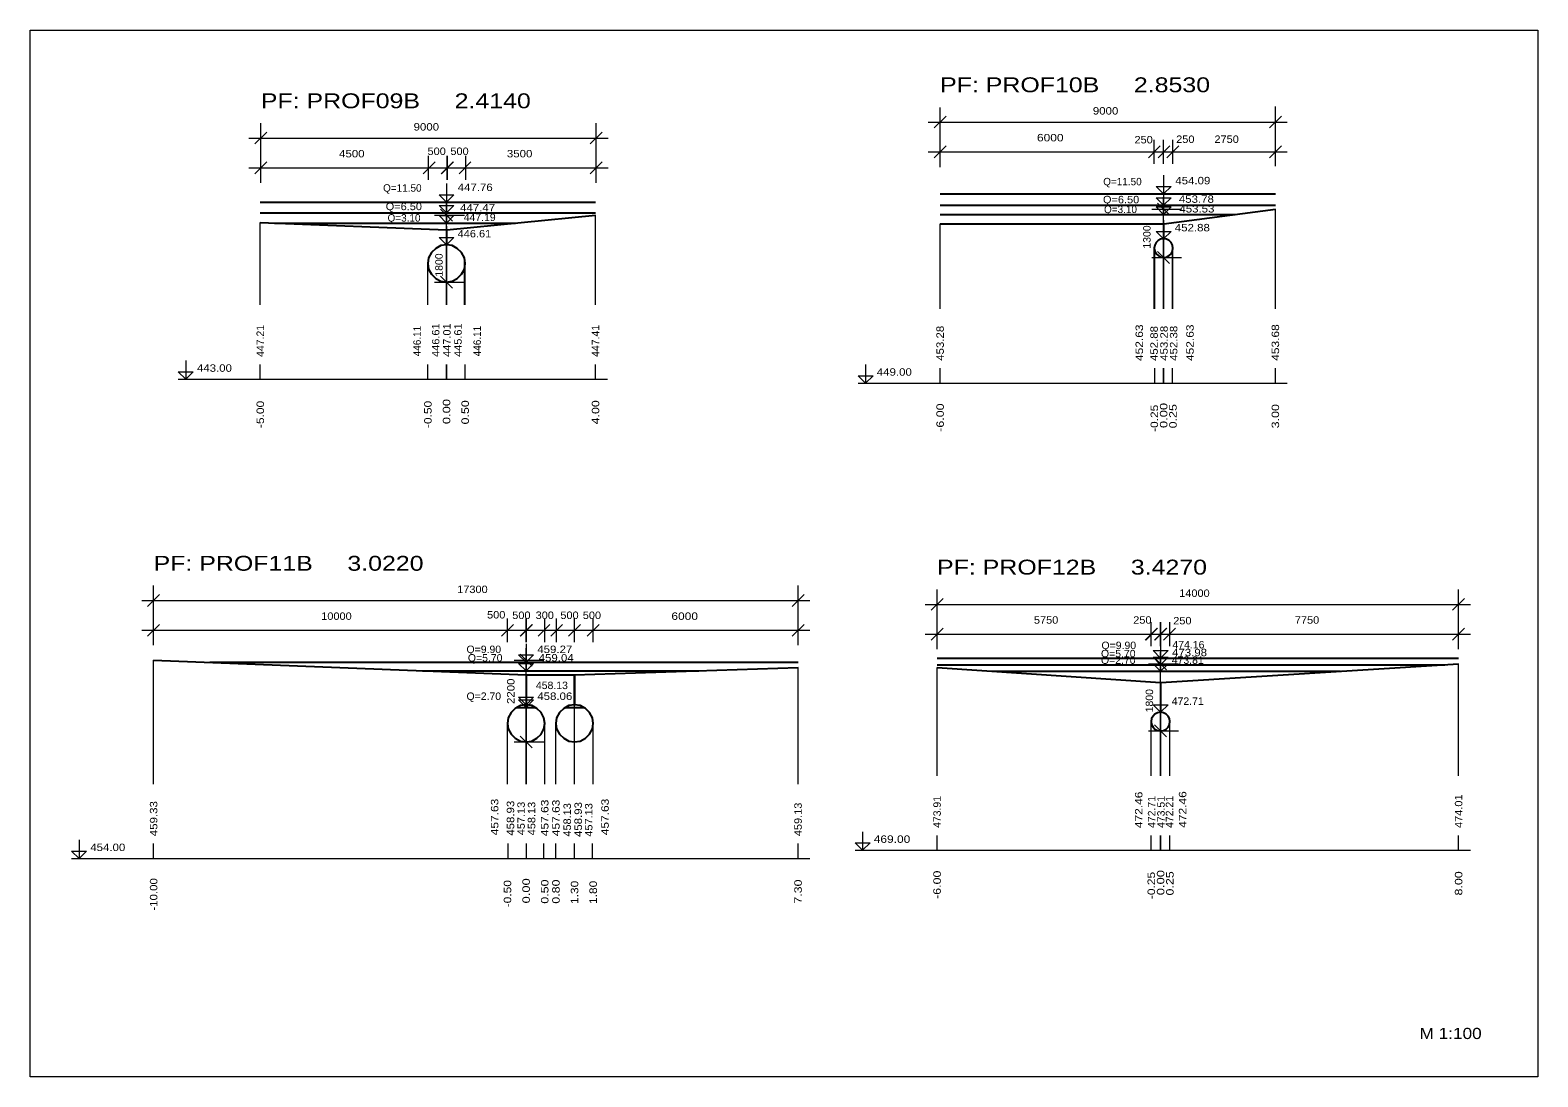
# Model space of a CAD drawing. Extents: x 7 to 442, y -393 to 441.
# Drawn here: x 17.93 to 58.4, y 45.74 to 73.86 of the extents above; entities that cross this region are included whole.
import ezdxf
from ezdxf.enums import TextEntityAlignment as Align

# ---------------------------------------------------------------- set-up
doc = ezdxf.new("R2010")
doc.units = 0
doc.header["$LTSCALE"] = 0.08
doc.header["$PDMODE"] = 32
doc.header["$PDSIZE"] = 0.04
doc.layers.add('63', color=7, linetype='Continuous', lineweight=13)
doc.layers.add('7', color=7, linetype='Continuous', lineweight=13)

msp = doc.modelspace()

# ---------------------------------------------------------------- linework, layer by layer
at = {"layer": '63'}
msp.add_lwpolyline([(17.927, 45.74), (17.927, 73.856), (38.164, 73.856), (58.401, 73.856), (58.401, 45.74), (38.164, 45.74)], close=True, dxfattribs=at)
at = {"layer": '7'}
for p, q in [((42.355, 70.174), (42.355, 71.774)), ((51.355, 70.201), (51.355, 71.801)), ((24.12, 69.758), (24.12, 71.358)), ((33.12, 69.758), (33.12, 71.358)), ((42.035, 71.388), (51.675, 71.388)), ((42.195, 71.228), (42.515, 71.548)), ((51.195, 71.228), (51.515, 71.548)), ((23.8, 70.958), (33.44, 70.958)), ((23.96, 70.798), (24.28, 71.118)), ((32.96, 70.798), (33.28, 71.118)), ((42.355, 70.268), (42.355, 70.908)), ((48.105, 70.268), (48.105, 70.908)), ((48.355, 70.268), (48.355, 70.908)), ((48.355, 70.268), (48.355, 70.908)), ((48.355, 70.268), (48.355, 70.908)), ((48.605, 70.268), (48.605, 70.908)), ((51.355, 70.268), (51.355, 70.908)), ((24.12, 69.838), (24.12, 70.478)), ((28.62, 69.838), (28.62, 70.478)), ((29.12, 69.838), (29.12, 70.478)), ((29.12, 69.838), (29.12, 70.478)), ((29.12, 69.838), (29.12, 70.478)), ((29.13, 69.838), (29.13, 70.478)), ((29.13, 69.838), (29.13, 70.478)), ((29.62, 69.838), (29.62, 70.478)), ((33.12, 69.838), (33.12, 70.478)), ((42.035, 70.588), (51.675, 70.588)), ((42.195, 70.428), (42.515, 70.748)), ((47.945, 70.428), (48.265, 70.748)), ((48.205, 70.428), (48.525, 70.748)), ((48.205, 70.428), (48.525, 70.748)), ((48.445, 70.428), (48.765, 70.748)), ((51.195, 70.428), (51.515, 70.748)), ((23.8, 70.158), (33.44, 70.158)), ((23.96, 69.998), (24.28, 70.318)), ((28.48, 69.998), (28.8, 70.318)), ((28.96, 69.998), (29.28, 70.318)), ((28.96, 69.998), (29.28, 70.318)), ((28.96, 69.998), (29.28, 70.318)), ((28.97, 69.998), (29.29, 70.318)), ((28.97, 69.998), (29.29, 70.318)), ((29.44, 69.998), (29.76, 70.318)), ((29.44, 69.998), (29.76, 70.318)), ((32.96, 69.998), (33.28, 70.318)), ((48.515, 68.891), (48.195, 69.211)), ((48.355, 67.591), (48.355, 69.371)), ((28.784, 68.889), (29.584, 68.889)), ((29.264, 68.729), (28.944, 69.049)), ((29.104, 66.929), (29.104, 69.209)), ((33.104, 66.479), (33.104, 68.889)), ((48.035, 69.051), (48.835, 69.051)), ((51.355, 66.374), (51.355, 69.051)), ((24.104, 66.479), (24.104, 68.689)), ((29.104, 66.479), (29.104, 68.489)), ((29.114, 66.479), (29.114, 68.489)), ((42.355, 66.374), (42.355, 68.651)), ((48.355, 66.374), (48.355, 68.651)), ((48.365, 66.374), (48.365, 68.651)), ((29.104, 66.479), (29.104, 68.089)), ((29.104, 68.089), (29.114, 68.089)), ((29.114, 66.479), (29.114, 68.089)), ((48.105, 66.374), (48.105, 68.001)), ((48.115, 66.374), (48.115, 68.081)), ((48.355, 66.374), (48.355, 68.251)), ((48.355, 68.251), (48.365, 68.251)), ((48.365, 66.374), (48.365, 68.251)), ((48.595, 66.374), (48.595, 68.081)), ((48.605, 66.374), (48.605, 68.001)), ((29.584, 66.479), (29.584, 67.739)), ((48.035, 67.751), (48.835, 67.751)), ((48.115, 66.374), (48.115, 67.921)), ((48.515, 67.591), (48.195, 67.911)), ((48.355, 66.374), (48.355, 67.751)), ((48.595, 66.374), (48.595, 67.921)), ((28.604, 66.479), (28.604, 67.589)), ((29.264, 66.929), (28.944, 67.249)), ((29.604, 66.479), (29.604, 67.589)), ((28.784, 67.089), (29.584, 67.089)), ((29.104, 66.479), (29.104, 67.089)), ((24.104, 64.479), (24.104, 64.879)), ((28.604, 64.479), (28.604, 64.879)), ((29.104, 64.479), (29.104, 64.879)), ((29.104, 64.479), (29.104, 64.879)), ((29.104, 64.479), (29.104, 64.879)), ((29.114, 64.479), (29.114, 64.879)), ((29.114, 64.479), (29.114, 64.879)), ((29.604, 64.479), (29.604, 64.879)), ((33.104, 64.479), (33.104, 64.879)), ((42.355, 64.374), (42.355, 64.774)), ((48.115, 64.374), (48.115, 64.774)), ((48.355, 64.374), (48.355, 64.774)), ((48.365, 64.374), (48.365, 64.774)), ((48.365, 64.374), (48.365, 64.774)), ((48.595, 64.374), (48.595, 64.774)), ((51.355, 64.374), (51.355, 64.774)), ((21.904, 64.479), (33.424, 64.479)), ((40.155, 64.374), (51.675, 64.374)), ((21.081, 58.375), (21.401, 58.695)), ((21.241, 57.335), (21.241, 58.935)), ((38.381, 58.375), (38.701, 58.695)), ((38.541, 57.335), (38.541, 58.935)), ((42.273, 57.232), (42.273, 58.832)), ((56.273, 57.232), (56.273, 58.832)), ((20.921, 58.535), (38.861, 58.535)), ((41.953, 58.432), (56.593, 58.432)), ((42.113, 58.272), (42.433, 58.592)), ((56.113, 58.272), (56.433, 58.592)), ((21.081, 57.575), (21.401, 57.895)), ((21.241, 57.415), (21.241, 58.055)), ((30.581, 57.575), (30.901, 57.895)), ((30.741, 57.415), (30.741, 58.055)), ((31.081, 57.575), (31.401, 57.895)), ((31.081, 57.575), (31.401, 57.895)), ((31.091, 57.575), (31.411, 57.895)), ((31.091, 57.575), (31.411, 57.895)), ((31.241, 57.415), (31.241, 58.055)), ((31.241, 57.415), (31.241, 58.055)), ((31.241, 57.415), (31.241, 58.055)), ((31.251, 57.415), (31.251, 58.055)), ((31.561, 57.575), (31.881, 57.895)), ((31.741, 57.415), (31.741, 58.055)), ((31.901, 57.575), (32.221, 57.895)), ((31.901, 57.575), (32.221, 57.895)), ((32.061, 57.415), (32.061, 58.055)), ((32.061, 57.415), (32.061, 58.055)), ((32.381, 57.575), (32.701, 57.895)), ((32.381, 57.575), (32.701, 57.895)), ((32.381, 57.575), (32.701, 57.895)), ((32.381, 57.575), (32.701, 57.895)), ((32.381, 57.575), (32.701, 57.895)), ((32.541, 57.415), (32.541, 58.055)), ((32.541, 57.415), (32.541, 58.055)), ((32.541, 57.415), (32.541, 58.055)), ((32.541, 57.415), (32.541, 58.055)), ((32.541, 57.415), (32.541, 58.055)), ((32.881, 57.575), (33.201, 57.895)), ((33.041, 57.415), (33.041, 58.055)), ((38.381, 57.575), (38.701, 57.895)), ((38.541, 57.415), (38.541, 58.055)), ((42.273, 57.312), (42.273, 57.952)), ((48.023, 57.312), (48.023, 57.952)), ((48.273, 57.312), (48.273, 57.952)), ((48.273, 57.312), (48.273, 57.952)), ((48.273, 57.312), (48.273, 57.952)), ((48.283, 57.312), (48.283, 57.952)), ((48.283, 57.312), (48.283, 57.952)), ((48.523, 57.312), (48.523, 57.952)), ((56.273, 57.312), (56.273, 57.952)), ((20.921, 57.735), (38.861, 57.735)), ((41.953, 57.632), (56.593, 57.632)), ((42.113, 57.472), (42.433, 57.792)), ((47.863, 57.472), (48.183, 57.792)), ((47.873, 57.472), (48.193, 57.792)), ((48.113, 57.472), (48.433, 57.792)), ((48.113, 57.472), (48.433, 57.792)), ((48.123, 57.472), (48.443, 57.792)), ((48.123, 57.472), (48.443, 57.792)), ((48.353, 57.472), (48.673, 57.792)), ((48.353, 57.472), (48.673, 57.792)), ((56.113, 57.472), (56.433, 57.792)), ((31.401, 56.775), (31.081, 57.095)), ((31.241, 54.575), (31.241, 57.255)), ((48.273, 54.872), (48.273, 57.152)), ((21.241, 53.605), (21.241, 56.935)), ((30.921, 56.935), (31.721, 56.935)), ((38.541, 53.605), (38.541, 56.735)), ((42.273, 53.826), (42.273, 56.732)), ((47.953, 56.832), (48.753, 56.832)), ((48.433, 56.672), (48.113, 56.992)), ((56.273, 53.826), (56.273, 56.832)), ((31.241, 53.605), (31.241, 56.535)), ((31.251, 53.605), (31.251, 56.535)), ((32.541, 53.605), (32.541, 56.535)), ((32.541, 53.605), (32.541, 56.535)), ((48.273, 53.826), (48.273, 56.332)), ((48.283, 53.826), (48.283, 56.332)), ((31.241, 53.605), (31.241, 55.735)), ((31.241, 55.735), (31.251, 55.735)), ((31.251, 53.605), (31.251, 55.735)), ((32.541, 53.605), (32.541, 55.735)), ((32.541, 53.605), (32.541, 55.735)), ((48.273, 53.826), (48.273, 55.532)), ((48.273, 55.532), (48.283, 55.532)), ((48.283, 53.826), (48.283, 55.532)), ((30.741, 53.605), (30.741, 55.235)), ((31.741, 53.605), (31.741, 55.235)), ((32.041, 53.605), (32.041, 55.235)), ((33.041, 53.605), (33.041, 55.235)), ((48.023, 53.826), (48.023, 55.282)), ((48.433, 54.872), (48.113, 55.192)), ((48.523, 53.826), (48.523, 55.282)), ((30.921, 54.735), (31.721, 54.735)), ((31.401, 54.575), (31.081, 54.895)), ((31.241, 53.605), (31.241, 54.735)), ((32.541, 53.605), (32.541, 54.735)), ((47.953, 55.032), (48.753, 55.032)), ((48.273, 53.826), (48.273, 55.032)), ((42.273, 51.826), (42.273, 52.226)), ((48.023, 51.826), (48.023, 52.226)), ((48.273, 51.826), (48.273, 52.226)), ((48.283, 51.826), (48.283, 52.226)), ((48.283, 51.826), (48.283, 52.226)), ((48.523, 51.826), (48.523, 52.226)), ((56.273, 51.826), (56.273, 52.226)), ((21.241, 51.605), (21.241, 52.005)), ((30.761, 51.605), (30.761, 52.005)), ((31.251, 51.605), (31.251, 52.005)), ((31.251, 51.605), (31.251, 52.005)), ((31.721, 51.605), (31.721, 52.005)), ((32.041, 51.605), (32.041, 52.005)), ((32.541, 51.605), (32.541, 52.005)), ((32.541, 51.605), (32.541, 52.005)), ((32.541, 51.605), (32.541, 52.005)), ((32.541, 51.605), (32.541, 52.005)), ((32.541, 51.605), (32.541, 52.005)), ((33.021, 51.605), (33.021, 52.005)), ((38.541, 51.605), (38.541, 52.005)), ((40.073, 51.826), (56.593, 51.826)), ((19.041, 51.605), (38.861, 51.605))]:
    msp.add_line(p, q, dxfattribs=at)
at = {"layer": '7', "lineweight": 25}
for p, q in [((24.104, 69.236), (33.104, 69.236)), ((42.355, 69.46), (51.355, 69.46)), ((24.104, 68.949), (33.104, 68.949)), ((42.355, 69.155), (51.355, 69.155)), ((42.355, 68.907), (50.277, 68.907)), ((24.49, 68.674), (30.955, 68.674)), ((22.749, 56.875), (38.541, 56.875)), ((42.273, 56.99), (56.273, 56.99)), ((42.273, 56.809), (55.901, 56.809)), ((28.459, 56.646), (35.88, 56.646)), ((43.749, 56.634), (53.102, 56.634)), ((31.004, 55.665), (31.478, 55.665)), ((32.304, 55.665), (32.778, 55.665))]:
    msp.add_line(p, q, dxfattribs=at)
at = {"layer": '7'}
for points in [[(29.104, 69.736), (29.104, 69.236), (28.904, 69.436), (29.304, 69.436), (29.104, 69.236)], [(48.355, 69.96), (48.355, 69.46), (48.155, 69.66), (48.555, 69.66), (48.355, 69.46)], [(48.355, 69.655), (48.355, 69.155), (48.155, 69.355), (48.555, 69.355), (48.355, 69.155)], [(29.104, 69.449), (29.104, 68.949), (28.904, 69.149), (29.304, 69.149), (29.104, 68.949)], [(48.355, 69.407), (48.355, 68.907), (48.155, 69.107), (48.555, 69.107), (48.355, 68.907)], [(29.104, 69.174), (29.104, 68.674), (28.904, 68.874), (29.304, 68.874), (29.104, 68.674)], [(29.104, 68.589), (29.104, 68.089), (28.904, 68.289), (29.304, 68.289), (29.104, 68.089)], [(48.355, 68.751), (48.355, 68.251), (48.155, 68.451), (48.555, 68.451), (48.355, 68.251)], [(22.104, 64.979), (22.104, 64.479), (21.904, 64.679), (22.304, 64.679), (22.104, 64.479)], [(40.355, 64.874), (40.355, 64.374), (40.155, 64.574), (40.555, 64.574), (40.355, 64.374)], [(48.273, 57.49), (48.273, 56.99), (48.073, 57.19), (48.473, 57.19), (48.273, 56.99)], [(31.241, 57.375), (31.241, 56.875), (31.041, 57.075), (31.441, 57.075), (31.241, 56.875)], [(31.241, 57.146), (31.241, 56.646), (31.041, 56.846), (31.441, 56.846), (31.241, 56.646)], [(48.273, 57.309), (48.273, 56.809), (48.073, 57.009), (48.473, 57.009), (48.273, 56.809)], [(48.273, 57.134), (48.273, 56.634), (48.073, 56.834), (48.473, 56.834), (48.273, 56.634)], [(31.241, 56.235), (31.241, 55.735), (31.041, 55.935), (31.441, 55.935), (31.241, 55.735)], [(31.241, 56.165), (31.241, 55.665), (31.041, 55.865), (31.441, 55.865), (31.241, 55.665)], [(48.273, 56.032), (48.273, 55.532), (48.073, 55.732), (48.473, 55.732), (48.273, 55.532)], [(40.273, 52.326), (40.273, 51.826), (40.073, 52.026), (40.473, 52.026), (40.273, 51.826)], [(19.241, 52.105), (19.241, 51.605), (19.041, 51.805), (19.441, 51.805), (19.241, 51.605)]]:
    msp.add_lwpolyline(points, dxfattribs=at)
at = {"layer": '7', "lineweight": 25}
for points in [[(24.104, 68.689), (29.104, 68.489), (29.104, 68.089), (28.954, 68.069), (28.814, 67.989), (28.704, 67.879), (28.624, 67.739), (28.604, 67.589), (28.624, 67.439), (28.704, 67.299), (28.814, 67.189), (28.954, 67.109), (29.104, 67.089), (29.254, 67.109), (29.394, 67.189), (29.504, 67.299), (29.584, 67.439), (29.604, 67.589), (29.584, 67.739), (29.504, 67.879), (29.394, 67.989), (29.254, 68.069), (29.114, 68.089), (29.114, 68.489), (33.104, 68.889)], [(42.355, 68.651), (48.355, 68.651), (48.355, 68.251), (48.275, 68.241), (48.205, 68.201), (48.155, 68.151), (48.115, 68.081), (48.105, 68.001), (48.115, 67.921), (48.155, 67.851), (48.205, 67.801), (48.275, 67.761), (48.355, 67.751), (48.435, 67.761), (48.505, 67.801), (48.555, 67.851), (48.595, 67.921), (48.605, 68.001), (48.595, 68.081), (48.555, 68.151), (48.505, 68.201), (48.435, 68.241), (48.365, 68.251), (48.365, 68.651), (51.355, 69.051)], [(21.241, 56.935), (31.241, 56.535), (31.241, 55.735), (31.091, 55.715), (30.951, 55.635), (30.841, 55.525), (30.761, 55.385), (30.741, 55.235), (30.761, 55.085), (30.841, 54.945), (30.951, 54.835), (31.091, 54.755), (31.241, 54.735), (31.391, 54.755), (31.531, 54.835), (31.641, 54.945), (31.721, 55.085), (31.741, 55.235), (31.721, 55.385), (31.641, 55.525), (31.531, 55.635), (31.391, 55.715), (31.251, 55.735), (31.251, 56.535), (32.541, 56.535), (32.541, 55.735), (32.391, 55.715), (32.251, 55.635), (32.141, 55.525), (32.061, 55.385), (32.041, 55.235), (32.061, 55.085), (32.141, 54.945), (32.251, 54.835), (32.391, 54.755), (32.541, 54.735), (32.691, 54.755), (32.831, 54.835), (32.941, 54.945), (33.021, 55.085), (33.041, 55.235), (33.021, 55.385), (32.941, 55.525), (32.831, 55.635), (32.691, 55.715), (32.541, 55.735), (32.541, 56.535), (38.541, 56.735)], [(42.273, 56.732), (48.273, 56.332), (48.273, 55.532), (48.193, 55.522), (48.123, 55.482), (48.073, 55.432), (48.033, 55.362), (48.023, 55.282), (48.033, 55.202), (48.073, 55.132), (48.123, 55.082), (48.193, 55.042), (48.273, 55.032), (48.353, 55.042), (48.423, 55.082), (48.473, 55.132), (48.513, 55.202), (48.523, 55.282), (48.513, 55.362), (48.473, 55.432), (48.423, 55.482), (48.353, 55.522), (48.283, 55.532), (48.283, 56.332), (56.273, 56.832)]]:
    msp.add_lwpolyline(points, dxfattribs=at)
at = {"layer": '7'}
msp.add_point((32.541, 55.735), dxfattribs=at)

# ---------------------------------------------------------------- texts
at = {"layer": '63', "width": 1.15}
msp.add_text('M 1:100', height=0.3, dxfattribs=at).set_placement((56.06, 46.756), align=Align.CENTER)
at = {"layer": '7'}
for s, height, width, p in [('PF: PROF10B     2.8530', 0.4, 1.25, (42.355, 72.188)), ('PF: PROF09B     2.4140', 0.4, 1.25, (24.12, 71.758)), ('9000', 0.2, 1.15, (46.455, 71.588)), ('9000', 0.2, 1.15, (28.22, 71.158)), ('6000', 0.2, 1.2, (44.955, 70.868)), ('250', 0.2, 1.1, (47.573, 70.813)), ('250', 0.2, 1.1, (48.692, 70.826)), ('2750', 0.2, 1.1, (49.719, 70.827)), ('4500', 0.2, 1.15, (26.22, 70.438)), ('500', 0.2, 1.1, (28.594, 70.503)), ('500', 0.2, 1.1, (29.208, 70.503)), ('3500', 0.2, 1.15, (30.725, 70.438)), ('447.76', 0.2, 1.15, (29.404, 69.533)), ('454.09', 0.2, 1.15, (48.669, 69.715)), ('Q=6.50', 0.2, 1.1, (27.472, 69.02)), ('Q=6.50', 0.2, 1.1, (46.727, 69.205)), ('453.78', 0.2, 1.15, (48.764, 69.218)), ('447.47', 0.2, 1.15, (29.469, 68.987)), ('447.19', 0.2, 1.05, (29.565, 68.729)), ('453.53', 0.2, 1.15, (48.778, 68.957)), ('446.61', 0.2, 1.1, (29.404, 68.289)), ('452.88', 0.2, 1.15, (48.655, 68.451)), ('443.00', 0.2, 1.15, (22.404, 64.679)), ('449.00', 0.2, 1.15, (40.655, 64.574)), ('PF: PROF11B     3.0220', 0.4, 1.25, (21.241, 59.335)), ('PF: PROF12B     3.4270', 0.4, 1.25, (42.273, 59.232)), ('17300', 0.2, 1.1, (29.391, 58.735)), ('14000', 0.2, 1.1, (48.773, 58.632)), ('10000', 0.2, 1.1, (25.741, 58.015)), ('500', 0.2, 1.1, (30.193, 58.052)), ('500', 0.2, 1.1, (30.869, 58.039)), ('300', 0.2, 1.1, (31.496, 58.04)), ('500', 0.2, 1.1, (32.16, 58.04)), ('500', 0.2, 1.1, (32.762, 58.039)), ('6000', 0.2, 1.2, (35.141, 58.015)), ('5750', 0.2, 1.1, (44.873, 57.912)), ('250', 0.2, 1.1, (47.539, 57.912)), ('250', 0.2, 1.1, (48.613, 57.894)), ('7750', 0.2, 1.1, (51.878, 57.912)), ('Q=9.90', 0.2, 1.05, (29.641, 57.124)), ('Q=5.70', 0.2, 1.05, (29.678, 56.895)), ('459.27', 0.2, 1.15, (31.541, 57.124)), ('459.04', 0.2, 1.15, (31.578, 56.896)), ('Q=5.70', 0.2, 1.05, (46.673, 57.009)), ('Q=9.90', 0.2, 1.05, (46.687, 57.23)), ('473.98', 0.2, 1.15, (48.58, 57.038)), ('474.16', 0.2, 1.05, (48.591, 57.248)), ('Q=2.70', 0.2, 1.05, (46.673, 56.834)), ('473.81', 0.2, 1.05, (48.573, 56.834)), ('458.13', 0.2, 1.05, (31.504, 56.156)), ('Q=2.70', 0.2, 1.05, (29.641, 55.865)), ('458.06', 0.2, 1.15, (31.541, 55.865)), ('472.71', 0.2, 1.05, (48.573, 55.732)), ('469.00', 0.2, 1.2, (40.573, 52.026)), ('454.00', 0.2, 1.15, (19.541, 51.805))]:
    msp.add_text(s, height=height, dxfattribs=dict(at, width=width)).set_placement(p)
for s, p in [('Q=11.50', (27.401, 69.517)), ('Q=11.50', (46.733, 69.688)), ('Q=3.10', (27.521, 68.713)), ('Q=3.10', (46.755, 68.943))]:
    msp.add_text(s, height=0.2, dxfattribs=at).set_placement(p)
for s, width, p in [('1300', 1.05, (48.005, 67.987)), ('1800', 1.05, (29.001, 67.234)), ('447.21 ', 1.05, (24.204, 65.079)), ('446.61 ', 1.1, (28.913, 65.079)), ('447.01 ', 1.1, (29.214, 65.079)), ('445.61 ', 1.1, (29.511, 65.079)), ('447.41 ', 1.05, (33.204, 65.079)), ('453.28 ', 1.15, (42.455, 64.974)), ('452.63 ', 1.2, (47.801, 64.968)), ('452.88 ', 1.15, (48.198, 64.968)), ('453.28 ', 1.15, (48.465, 64.974)), ('452.38 ', 1.15, (48.724, 64.974)), ('452.63 ', 1.2, (49.163, 64.968)), ('453.68 ', 1.2, (51.455, 64.974)), (' -5.00 ', 1.2, (24.204, 63.079)), (' -0.50 ', 1.2, (28.704, 63.079)), ('  0.00 ', 1.3, (29.204, 63.079)), ('  0.00 ', 1.3, (29.204, 63.079)), ('  0.50 ', 1.25, (29.704, 63.079)), ('  4.00 ', 1.25, (33.204, 63.079)), (' -6.00 ', 1.25, (42.455, 62.974)), (' -0.25 ', 1.2, (48.205, 62.974)), ('  0.00 ', 1.3, (48.455, 62.974)), ('  0.00 ', 1.3, (48.455, 62.974)), ('  0.00 ', 1.3, (48.455, 62.974)), ('  0.25 ', 1.25, (48.705, 62.974)), ('  3.00 ', 1.25, (51.455, 62.974)), ('2200', 1.15, (30.93, 55.755)), ('1800', 1.05, (48.073, 55.532)), ('459.33 ', 1.15, (21.341, 52.205)), ('457.63 ', 1.2, (30.496, 52.229)), ('458.93 ', 1.15, (30.921, 52.217)), ('457.13 ', 1.1, (31.206, 52.23)), ('458.13 ', 1.1, (31.487, 52.229)), ('457.63 ', 1.2, (31.841, 52.205)), ('457.63 ', 1.2, (32.141, 52.205)), ('458.13 ', 1.1, (32.444, 52.193)), ('458.93 ', 1.15, (32.739, 52.181)), ('457.13 ', 1.1, (33.022, 52.192)), ('457.63 ', 1.2, (33.46, 52.23)), ('459.13 ', 1.1, (38.641, 52.205)), ('473.91 ', 1.05, (42.373, 52.426)), ('472.46 ', 1.2, (47.786, 52.421)), ('472.71 ', 1.05, (48.132, 52.426)), ('473.51 ', 1.05, (48.383, 52.426)), ('472.21 ', 1.05, (48.613, 52.426)), ('472.46 ', 1.2, (48.964, 52.431)), ('474.01 ', 1.1, (56.373, 52.426)), ('-10.00 ', 1.15, (21.341, 50.205)), (' -0.50 ', 1.2, (30.841, 50.205)), ('  0.00 ', 1.3, (31.341, 50.205)), ('  0.00 ', 1.3, (31.341, 50.205)), ('  0.00 ', 1.3, (31.341, 50.205)), ('  0.50 ', 1.25, (31.841, 50.205)), ('  0.80 ', 1.25, (32.141, 50.205)), ('  7.30 ', 1.25, (38.641, 50.205)), (' -6.00 ', 1.25, (42.373, 50.426)), (' -0.25 ', 1.2, (48.123, 50.426)), ('  0.00 ', 1.3, (48.373, 50.426)), ('  0.00 ', 1.3, (48.373, 50.426)), ('  0.00 ', 1.3, (48.373, 50.426)), ('  0.25 ', 1.25, (48.623, 50.426)), ('  8.00 ', 1.25, (56.373, 50.426)), ('  1.30 ', 1.2, (32.641, 50.205)), ('  1.30 ', 1.2, (32.641, 50.205)), ('  1.30 ', 1.2, (32.641, 50.205)), ('  1.30 ', 1.2, (32.641, 50.205)), ('  1.30 ', 1.2, (32.641, 50.205)), ('  1.80 ', 1.2, (33.141, 50.205))]:
    msp.add_text(s, height=0.2, rotation=90, dxfattribs=dict(at, width=width)).set_placement(p)
for p in [(28.413, 65.095), (30.027, 65.095)]:
    msp.add_text('446.11 ', height=0.2, rotation=90, dxfattribs=at).set_placement(p)

doc.saveas('drawing.dxf')
